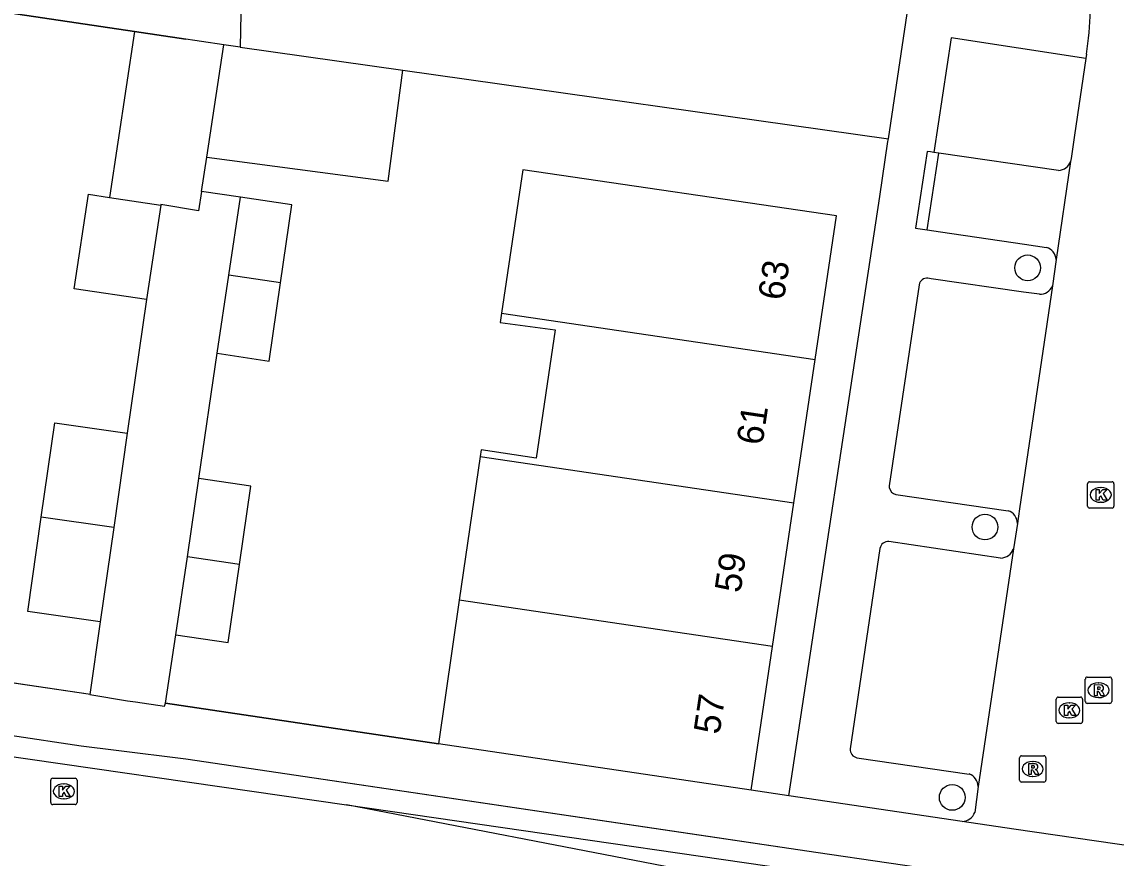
# Model space of a CAD drawing. Extents: x 164150 to 165261, y 382513 to 383432.
# Drawn here: x 164559.95 to 164601.52, y 383187.53 to 383219.29 of the extents above; entities that cross this region are included whole.
import ezdxf

# ---------------------------------------------------------------- set-up
doc = ezdxf.new("R2010")
doc.units = 0
for name, color, linetype in [('IMGEO_Boom', 7, 'Continuous'), ('IMGEO_Greppel_droge_sloot', 7, 'Continuous'), ('IMGEO_Groenvoorziening', 7, 'Continuous'), ('IMGEO_Haag', 7, 'Continuous'), ('IMGEO_Kolk', 7, 'Continuous'), ('IMGEO_Muur', 7, 'Continuous'), ('IMGEO_Pand', 7, 'Continuous'), ('IMGEO_Pand_nummerreeks', 7, 'Continuous'), ('IMGEO_Parkeervlak_open', 7, 'Continuous'), ('IMGEO_Rijbaan_lokaal_open', 7, 'Continuous'), ('IMGEO_Rioolput', 7, 'Continuous'), ('IMGEO_Voetpad_open', 7, 'Continuous')]:
    doc.layers.add(name, color=color, linetype=linetype)

msp = doc.modelspace()

# ---------------------------------------------------------------- linework, layer by layer
at = {"layer": 'IMGEO_Boom'}
for centre in [(164598.163, 383209.948), (164596.542, 383200.103), (164595.299, 383189.832)]:
    msp.add_circle(centre, 0.489, dxfattribs=at)
at = {"layer": 'IMGEO_Greppel_droge_sloot'}
for points in [[(164556.654, 383191.81), (164572.277, 383189.545)], [(164573.412, 383184.526), (164584.995, 383182.76), (164586.627, 383182.516), (164587.865, 383182.331), (164588.958, 383182.99), (164588.919, 383183.59), (164589.007, 383184.099), (164589.029, 383184.645), (164589.051, 383185.183), (164586.126, 383186.957), (164584.737, 383187.145), (164572.277, 383189.545)]]:
    msp.add_lwpolyline(points, dxfattribs=at)
at = {"layer": 'IMGEO_Groenvoorziening'}
for points in [[(164590.192, 383226.957), (164589.864, 383225.37), (164589.304, 383222.659), (164588.503, 383222.765), (164588.039, 383223.46), (164587.311, 383223.56), (164586.384, 383222.732), (164570.88, 383224.66), (164568.363, 383224.706), (164568.247, 383218.335)], [(164564.232, 383218.921), (164557.219, 383219.961)], [(164574.417, 383217.46), (164592.871, 383214.844)]]:
    msp.add_lwpolyline(points, dxfattribs=at)
at = {"layer": 'IMGEO_Haag'}
for points in [[(164590.121, 383187.743), (164566.178, 383191.288)], [(164572.277, 383189.545), (164594.994, 383186.254)]]:
    msp.add_lwpolyline(points, dxfattribs=at)
at = {"layer": 'IMGEO_Kolk'}
for p, q in [((164600.442, 383200.897), (164600.442, 383201.749)), ((164600.517, 383201.823), (164601.369, 383201.823)), ((164601.443, 383201.749), (164601.443, 383200.897)), ((164600.93, 383201.603), (164600.955, 383201.603)), ((164600.953, 383201.043), (164600.928, 383201.043)), ((164601.369, 383200.823), (164600.517, 383200.823)), ((164599.248, 383192.715), (164599.248, 383193.567)), ((164599.323, 383193.641), (164600.175, 383193.641)), ((164599.736, 383193.421), (164599.761, 383193.421)), ((164600.249, 383193.567), (164600.249, 383192.715)), ((164600.175, 383192.641), (164599.323, 383192.641)), ((164599.759, 383192.861), (164599.734, 383192.861)), ((164561.043, 383189.637), (164561.043, 383190.489)), ((164561.118, 383190.563), (164561.97, 383190.563)), ((164562.044, 383190.489), (164562.044, 383189.637)), ((164561.531, 383190.343), (164561.556, 383190.343)), ((164561.554, 383189.783), (164561.529, 383189.783)), ((164561.97, 383189.563), (164561.118, 383189.563))]:
    msp.add_line(p, q, dxfattribs=at)
for points in [[(164600.442, 383200.897), (164600.442, 383201.749)], [(164600.517, 383201.823), (164601.369, 383201.823)], [(164601.443, 383201.749), (164601.443, 383200.897)], [(164600.763, 383201.523), (164600.886, 383201.523), (164600.886, 383201.372), (164601.016, 383201.523), (164601.18, 383201.523), (164601.034, 383201.372), (164601.187, 383201.123), (164601.035, 383201.123), (164600.95, 383201.287), (164600.886, 383201.22), (164600.886, 383201.123), (164600.763, 383201.123), (164600.763, 383201.523)], [(164601.369, 383200.823), (164600.517, 383200.823)], [(164599.248, 383192.715), (164599.248, 383193.567)], [(164599.323, 383193.641), (164600.175, 383193.641)], [(164600.249, 383193.567), (164600.249, 383192.715)], [(164599.569, 383193.341), (164599.692, 383193.341), (164599.692, 383193.19), (164599.822, 383193.341), (164599.986, 383193.341), (164599.84, 383193.19), (164599.993, 383192.941), (164599.841, 383192.941), (164599.756, 383193.105), (164599.692, 383193.038), (164599.692, 383192.941), (164599.569, 383192.941), (164599.569, 383193.341)], [(164600.175, 383192.641), (164599.323, 383192.641)], [(164561.043, 383189.637), (164561.043, 383190.489)], [(164561.118, 383190.563), (164561.97, 383190.563)], [(164562.044, 383190.489), (164562.044, 383189.637)], [(164561.364, 383190.263), (164561.487, 383190.263), (164561.487, 383190.112), (164561.617, 383190.263), (164561.781, 383190.263), (164561.635, 383190.112), (164561.788, 383189.863), (164561.636, 383189.863), (164561.551, 383190.027), (164561.487, 383189.96), (164561.487, 383189.863), (164561.364, 383189.863), (164561.364, 383190.263)], [(164561.97, 383189.563), (164561.118, 383189.563)]]:
    msp.add_lwpolyline(points, dxfattribs=at)
for centre, start, end in [((164600.519, 383201.747), 91.552, 178.448), ((164600.519, 383201.747), 91.552, 178.448), ((164601.367, 383201.747), 1.552, 88.448), ((164601.367, 383201.747), 1.552, 88.448), ((164600.519, 383200.899), 181.552, 268.448), ((164600.519, 383200.899), 181.552, 268.448), ((164601.367, 383200.899), 271.552, 358.448), ((164601.367, 383200.899), 271.552, 358.448), ((164599.325, 383193.565), 91.552, 178.448), ((164599.325, 383193.565), 91.552, 178.448), ((164600.173, 383193.565), 1.552, 88.448), ((164600.173, 383193.565), 1.552, 88.448), ((164599.325, 383192.717), 181.552, 268.448), ((164599.325, 383192.717), 181.552, 268.448), ((164600.173, 383192.717), 271.552, 358.448), ((164600.173, 383192.717), 271.552, 358.448), ((164561.12, 383190.487), 91.552, 178.448), ((164561.12, 383190.487), 91.552, 178.448), ((164561.968, 383190.487), 1.552, 88.448), ((164561.968, 383190.487), 1.552, 88.448), ((164561.12, 383189.639), 181.552, 268.448), ((164561.12, 383189.639), 181.552, 268.448), ((164561.968, 383189.639), 271.552, 358.448), ((164561.968, 383189.639), 271.552, 358.448)]:
    msp.add_arc(centre, 0.0765, start, end, dxfattribs=at)
for centre, major_axis, ratio, start_param, end_param in [((164600.929, 383201.323), (-0.387, 0.002), 0.722429, 4.712389, 7.853982), ((164600.954, 383201.323), (-0.39, 0.002), 0.717154, 1.570796, 4.712389), ((164599.735, 383193.141), (-0.387, 0.002), 0.722429, 4.712389, 7.853982), ((164599.76, 383193.141), (-0.39, 0.002), 0.717154, 1.570796, 4.712389), ((164561.53, 383190.063), (-0.387, 0.002), 0.722429, 4.712389, 7.853982), ((164561.555, 383190.063), (-0.39, 0.002), 0.717154, 1.570796, 4.712389)]:
    msp.add_ellipse(centre, major_axis=major_axis, ratio=ratio, start_param=start_param, end_param=end_param, dxfattribs=at)
at = {"layer": 'IMGEO_Muur'}
for points in [[(164557.219, 383219.961), (164564.232, 383218.921), (164566.179, 383218.635)], [(164562.532, 383193.748), (164562.467, 383193.759), (164550.593, 383195.514)], [(164563.956, 383193.506), (164564.263, 383193.461), (164565.369, 383193.297), (164565.399, 383193.408), (164575.772, 383191.872)]]:
    msp.add_lwpolyline(points, dxfattribs=at)
at = {"layer": 'IMGEO_Pand'}
for points in [[(164564.232, 383218.921), (164563.281, 383212.624)], [(164567.625, 383218.423), (164564.232, 383218.921)], [(164566.974, 383214.155), (164567.625, 383218.423)], [(164568.247, 383218.335), (164567.625, 383218.423)], [(164568.247, 383218.335), (164574.417, 383217.46)], [(164566.974, 383214.155), (164573.867, 383213.246), (164574.417, 383217.46)], [(164566.775, 383212.855), (164566.974, 383214.155)], [(164590.09, 383206.469), (164590.9, 383211.92), (164578.988, 383213.669), (164578.173, 383208.231)], [(164564.682, 383208.741), (164561.93, 383209.157), (164562.473, 383212.746), (164563.281, 383212.624)], [(164563.281, 383212.624), (164565.225, 383212.329)], [(164566.775, 383212.855), (164566.663, 383212.119), (164565.228, 383212.349), (164565.225, 383212.329)], [(164567.811, 383209.668), (164568.257, 383212.628)], [(164569.775, 383209.374), (164570.209, 383212.338), (164568.257, 383212.628)], [(164565.225, 383212.329), (164564.682, 383208.741)], [(164567.364, 383206.708), (164567.811, 383209.668)], [(164569.775, 383209.374), (164567.811, 383209.668)], [(164567.364, 383206.708), (164569.342, 383206.41), (164569.775, 383209.374)], [(164578.173, 383208.231), (164578.119, 383207.875), (164580.214, 383207.596), (164579.485, 383202.717), (164577.395, 383203.03), (164577.359, 383202.78)], [(164578.173, 383208.231), (164590.09, 383206.469)], [(164589.28, 383201.017), (164590.09, 383206.469)], [(164560.686, 383200.48), (164561.198, 383204.065), (164563.95, 383203.671)], [(164563.95, 383203.671), (164563.438, 383200.087)], [(164577.359, 383202.78), (164576.565, 383197.326)], [(164577.359, 383202.78), (164589.28, 383201.017)], [(164566.237, 383198.974), (164566.67, 383201.943)], [(164568.216, 383198.685), (164568.649, 383201.654), (164566.67, 383201.943)], [(164588.471, 383195.565), (164589.28, 383201.017)], [(164562.926, 383196.502), (164560.174, 383196.896), (164560.686, 383200.48)], [(164563.438, 383200.087), (164560.686, 383200.48)], [(164563.438, 383200.087), (164562.926, 383196.502)], [(164565.803, 383196.005), (164566.237, 383198.974)], [(164568.216, 383198.685), (164566.237, 383198.974)], [(164565.803, 383196.005), (164567.782, 383195.716), (164568.216, 383198.685)], [(164576.565, 383197.326), (164575.772, 383191.872)], [(164588.471, 383195.565), (164576.565, 383197.326)], [(164587.661, 383190.114), (164588.471, 383195.565)], [(164587.661, 383190.114), (164575.772, 383191.872)]]:
    msp.add_lwpolyline(points, dxfattribs=at)
at = {"layer": 'IMGEO_Parkeervlak_open'}
for points in [[(164594.34, 383211.388), (164594.79, 383214.301)], [(164594.79, 383214.301), (164594.603, 383214.33)], [(164599.34, 383213.651), (164594.79, 383214.301)]]:
    msp.add_lwpolyline(points, dxfattribs=at)
msp.add_arc((164599.32, 383214.154), 0.503, 272.2762, 341.1413, dxfattribs=at)
at = {"layer": 'IMGEO_Rijbaan_lokaal_open'}
for points in [[(164600.398, 383218.068), (164600.373, 383217.896)], [(164600.373, 383217.896), (164599.943, 383214.983), (164599.813, 383214.105), (164599.796, 383213.991)], [(164599.796, 383213.991), (164599.246, 383210.261)], [(164599.246, 383210.261), (164599.102, 383209.269)], [(164599.102, 383209.269), (164597.858, 383200.79), (164597.777, 383200.235)], [(164597.777, 383200.235), (164597.62, 383199.279)], [(164597.62, 383199.279), (164596.285, 383190.247)], [(164596.285, 383190.247), (164596.151, 383189.263)], [(164602.346, 383187.943), (164597.635, 383188.632), (164595.678, 383188.918)]]:
    msp.add_lwpolyline(points, dxfattribs=at)
for centre, radius, start, end in [((164587.365, 383220.095), 13.19, 351.158, 358.3081), ((164595.669, 383189.428), 0.51, 271.067, 341.1461)]:
    msp.add_arc(centre, radius, start, end, dxfattribs=at)
at = {"layer": 'IMGEO_Rioolput'}
for p, q in [((164600.355, 383193.478), (164600.355, 383194.33)), ((164600.43, 383194.404), (164601.282, 383194.404)), ((164601.356, 383194.33), (164601.356, 383193.478)), ((164600.843, 383194.184), (164600.868, 383194.184)), ((164601.282, 383193.404), (164600.43, 383193.404)), ((164600.866, 383193.624), (164600.841, 383193.624)), ((164597.855, 383190.487), (164597.855, 383191.339)), ((164597.93, 383191.413), (164598.782, 383191.413)), ((164598.856, 383191.339), (164598.856, 383190.487)), ((164598.343, 383191.193), (164598.368, 383191.193)), ((164598.366, 383190.633), (164598.341, 383190.633)), ((164598.782, 383190.413), (164597.93, 383190.413))]:
    msp.add_line(p, q, dxfattribs=at)
for points in [[(164600.355, 383193.478), (164600.355, 383194.33)], [(164600.43, 383194.404), (164601.282, 383194.404)], [(164601.356, 383194.33), (164601.356, 383193.478)], [(164600.944, 383194.102), (164600.692, 383194.104), (164600.692, 383193.704)], [(164600.692, 383193.704), (164600.816, 383193.704), (164600.816, 383193.866), (164600.827, 383193.866)], [(164600.87, 383194.023), (164600.816, 383194.023), (164600.816, 383193.942)], [(164600.816, 383193.942), (164600.868, 383193.942)], [(164600.874, 383193.837), (164600.945, 383193.704), (164601.085, 383193.704), (164601.02, 383193.83)], [(164601.282, 383193.404), (164600.43, 383193.404)], [(164597.855, 383190.487), (164597.855, 383191.339)], [(164597.93, 383191.413), (164598.782, 383191.413)], [(164598.856, 383191.339), (164598.856, 383190.487)], [(164598.444, 383191.111), (164598.192, 383191.113), (164598.192, 383190.713)], [(164598.192, 383190.713), (164598.316, 383190.713), (164598.316, 383190.875), (164598.327, 383190.875)], [(164598.37, 383191.032), (164598.316, 383191.032), (164598.316, 383190.951)], [(164598.316, 383190.951), (164598.368, 383190.951)], [(164598.374, 383190.846), (164598.445, 383190.713), (164598.585, 383190.713), (164598.52, 383190.839)], [(164598.782, 383190.413), (164597.93, 383190.413)]]:
    msp.add_lwpolyline(points, dxfattribs=at)
for centre, radius, start, end in [((164600.432, 383194.328), 0.0765, 91.552, 178.448), ((164600.432, 383194.328), 0.0765, 91.552, 178.448), ((164601.28, 383194.328), 0.0765, 1.552, 88.448), ((164601.28, 383194.328), 0.0765, 1.552, 88.448), ((164600.826, 383193.813), 0.0533, 26.0293, 88.6989), ((164600.852, 383194.131), 0.19, 274.7715, 282.9687), ((164600.876, 383193.927), 0.0964, 77.0061, 93.1865), ((164600.89, 383193.984), 0.0378, 276.6634, 79.6772), ((164600.943, 383193.992), 0.109, 350.3612, 89.416), ((164600.941, 383193.992), 0.112, 277.5842, 350.9817), ((164600.925, 383193.777), 0.108, 29.5134, 73.7905), ((164600.432, 383193.48), 0.0765, 181.552, 268.448), ((164600.432, 383193.48), 0.0765, 181.552, 268.448), ((164601.28, 383193.48), 0.0765, 271.552, 358.448), ((164601.28, 383193.48), 0.0765, 271.552, 358.448), ((164597.932, 383191.337), 0.0765, 91.552, 178.448), ((164597.932, 383191.337), 0.0765, 91.552, 178.448), ((164598.78, 383191.337), 0.0765, 1.552, 88.448), ((164598.78, 383191.337), 0.0765, 1.552, 88.448), ((164598.326, 383190.822), 0.0533, 26.0293, 88.6989), ((164598.352, 383191.14), 0.19, 274.7715, 282.9687), ((164598.376, 383190.936), 0.0964, 77.0061, 93.1865), ((164598.39, 383190.993), 0.0378, 276.6634, 79.6772), ((164598.443, 383191.001), 0.109, 350.3612, 89.416), ((164598.441, 383191.001), 0.112, 277.5842, 350.9817), ((164598.425, 383190.786), 0.108, 29.5134, 73.7905), ((164597.932, 383190.489), 0.0765, 181.552, 268.448), ((164597.932, 383190.489), 0.0765, 181.552, 268.448), ((164598.78, 383190.489), 0.0765, 271.552, 358.448), ((164598.78, 383190.489), 0.0765, 271.552, 358.448)]:
    msp.add_arc(centre, radius, start, end, dxfattribs=at)
for centre, major_axis, ratio, start_param, end_param in [((164600.842, 383193.904), (-0.387, 0.002), 0.722429, 4.712389, 7.853982), ((164600.867, 383193.904), (-0.39, 0.002), 0.717154, 1.570796, 4.712389), ((164598.342, 383190.913), (-0.387, 0.002), 0.722429, 4.712389, 7.853982), ((164598.367, 383190.913), (-0.39, 0.002), 0.717154, 1.570796, 4.712389)]:
    msp.add_ellipse(centre, major_axis=major_axis, ratio=ratio, start_param=start_param, end_param=end_param, dxfattribs=at)
at = {"layer": 'IMGEO_Voetpad_open'}
for points in [[(164592.871, 383214.844), (164594.315, 383224.55)], [(164600.373, 383217.896), (164595.26, 383218.687), (164594.603, 383214.33)], [(164589.091, 383189.893), (164592.546, 383212.662), (164592.856, 383214.748), (164592.871, 383214.844)], [(164594.603, 383214.33), (164594.468, 383214.351), (164594.343, 383214.37), (164593.902, 383211.451), (164594.34, 383211.388)], [(164568.257, 383212.628), (164566.775, 383212.855)], [(164594.34, 383211.388), (164594.854, 383211.312), (164598.043, 383210.843), (164598.879, 383210.72)], [(164594.039, 383209.309), (164592.903, 383201.672), (164592.903, 383201.64), (164592.905, 383201.608)], [(164598.609, 383208.945), (164598.01, 383209.031), (164594.498, 383209.536), (164594.377, 383209.553)], [(164564.682, 383208.741), (164563.95, 383203.671)], [(164566.67, 383201.943), (164567.364, 383206.708)], [(164593.159, 383201.336), (164597.421, 383200.723)], [(164592.552, 383199.291), (164591.421, 383191.679)], [(164597.138, 383198.925), (164592.895, 383199.549)], [(164562.926, 383196.502), (164562.532, 383193.748)], [(164565.399, 383193.408), (164565.803, 383196.005)], [(164562.532, 383193.748), (164562.467, 383193.759), (164553.529, 383195.067)], [(164562.532, 383193.748), (164563.956, 383193.506), (164564.263, 383193.461), (164565.369, 383193.297), (164565.399, 383193.408)], [(164575.772, 383191.872), (164565.399, 383193.408)], [(164566.178, 383191.288), (164563.531, 383191.613), (164562.196, 383191.777), (164556.788, 383192.585)], [(164591.676, 383191.341), (164595.94, 383190.722)], [(164590.121, 383187.743), (164585.681, 383188.394), (164566.178, 383191.288)], [(164589.091, 383189.893), (164587.661, 383190.114)], [(164595.678, 383188.918), (164589.091, 383189.893)], [(164595.665, 383186.93), (164590.121, 383187.743)]]:
    msp.add_lwpolyline(points, dxfattribs=at)
for centre, radius, start, end in [((164598.748, 383210.239), 0.499, 2.5601, 74.729), ((164594.339, 383209.249), 0.306, 82.9532, 168.6973), ((164598.638, 383209.438), 0.494, 266.6426, 339.9833), ((164593.225, 383201.652), 0.323, 187.8589, 258.2213), ((164597.268, 383200.238), 0.509, 359.7174, 72.5047), ((164592.855, 383199.245), 0.307, 82.5688, 171.3312), ((164597.126, 383199.446), 0.521, 271.3049, 341.2852), ((164591.733, 383191.649), 0.314, 174.5863, 259.4783), ((164595.763, 383190.231), 0.522, 1.8059, 70.177)]:
    msp.add_arc(centre, radius, start, end, dxfattribs=at)

# ---------------------------------------------------------------- texts
at = {"layer": 'IMGEO_Pand_nummerreeks'}
for s, p in [('63', (164588.902, 383208.683)), ('61', (164588.085, 383203.18)), ('59', (164587.252, 383197.573)), ('57', (164586.454, 383192.196))]:
    msp.add_text(s, height=1, rotation=81.5491, dxfattribs=at).set_placement(p)

doc.saveas('drawing.dxf')
